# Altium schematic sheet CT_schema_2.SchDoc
size 307 x 173 mm
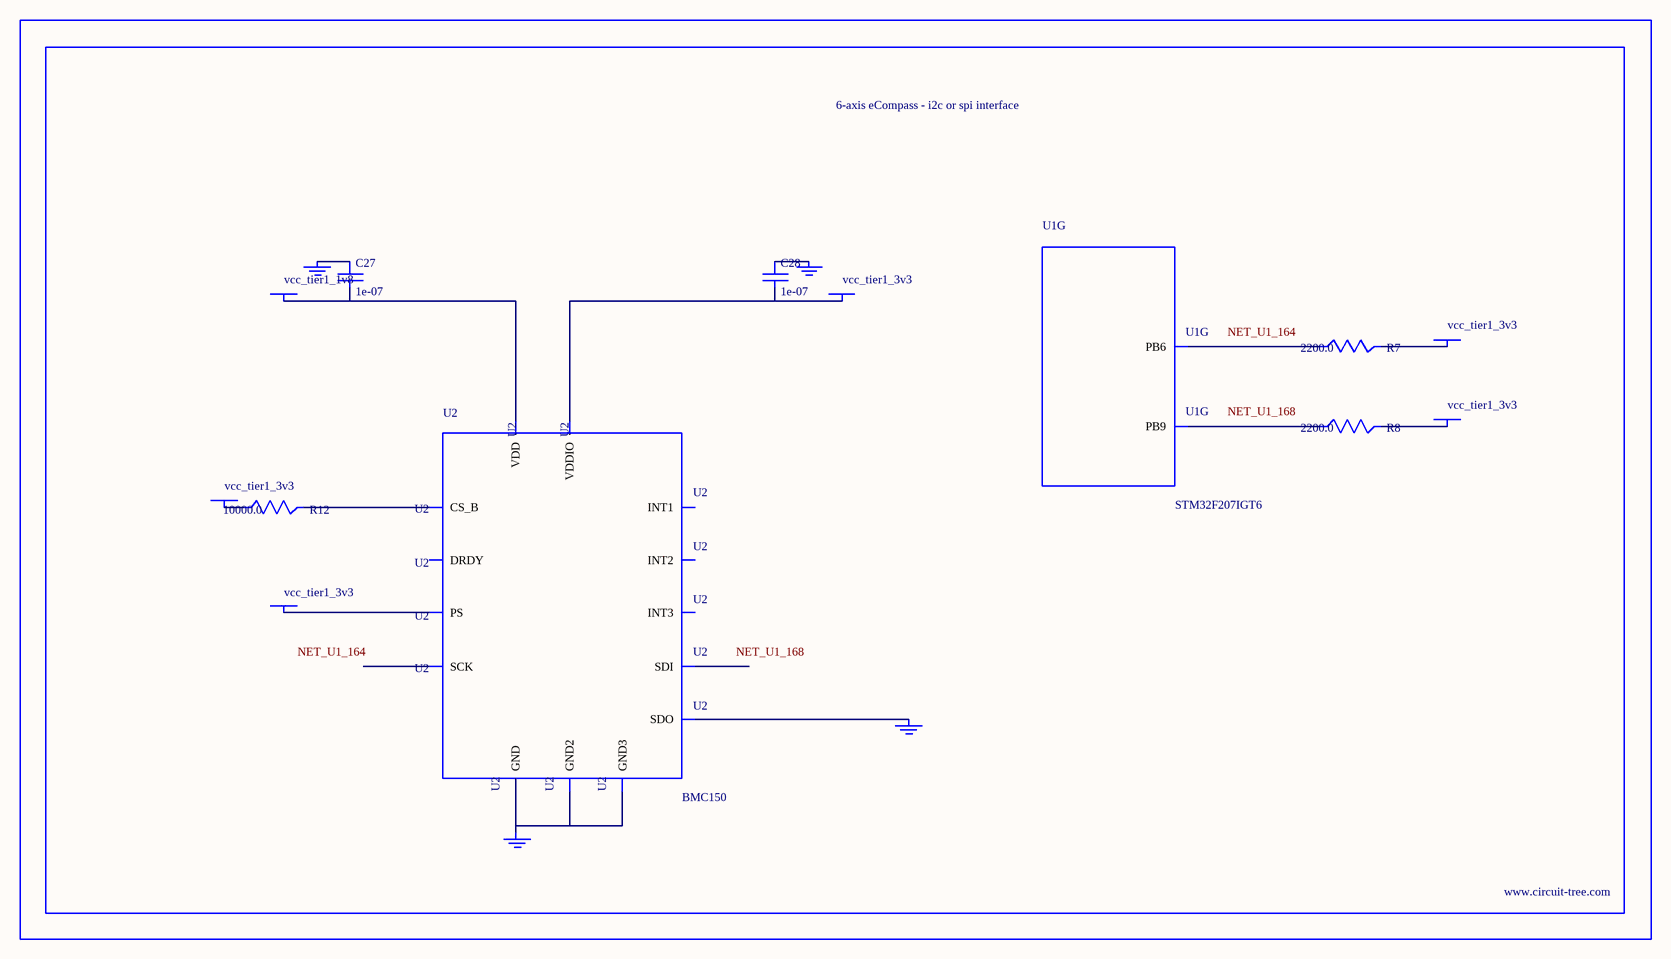
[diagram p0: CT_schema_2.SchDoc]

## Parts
BORDER1  (no value)
C27  1e-07  [C0402]
C28  1e-07  [C0402]
GND_INSTANCE_1_0  (no value)
GND_INSTANCE_1_1  (no value)
GND_INSTANCE_1_2  (no value)
GND_INSTANCE_1_3  (no value)
POWER_INSTANCE_1_0  vcc_tier1_1v8
POWER_INSTANCE_1_1  vcc_tier1_3v3
POWER_INSTANCE_1_2  vcc_tier1_3v3
POWER_INSTANCE_1_3  vcc_tier1_3v3
POWER_INSTANCE_1_4  vcc_tier1_3v3
POWER_INSTANCE_1_5  vcc_tier1_3v3
R7  2200.0  [R0603]
R8  2200.0  [R0603]
R12  10000.0  [R0603]
U1  STM32F207IGT6  [LQFP176]  (part G of 15)
U2  BMC150  [LGA14R35P5X6_200X200X100]

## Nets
NetC27_1: C27.1 GND_INSTANCE_1_1.0(GND)
NetC27_2: C27.2 POWER_INSTANCE_1_0.0(PWR) U2.8(VDD)
NetC28_1: C28.1 GND_INSTANCE_1_2.0(GND)
NetC28_2: C28.2 POWER_INSTANCE_1_1.0(PWR) U2.10(VDDIO)
NetGND_INSTANCE_1_0_0: GND_INSTANCE_1_0.0(GND) U2.1(SDO)
NetGND_INSTANCE_1_3_0: GND_INSTANCE_1_3.0(GND) U2.6(GND) U2.7(GND2) U2.9(GND3)
NetPOWER_INSTANCE_1_2_0: POWER_INSTANCE_1_2.0(PWR) R12.1
NetPOWER_INSTANCE_1_3_0: POWER_INSTANCE_1_3.0(PWR) U2.13(PS)
NetPOWER_INSTANCE_1_4_0: POWER_INSTANCE_1_4.0(PWR) R7.2
NetPOWER_INSTANCE_1_5_0: POWER_INSTANCE_1_5.0(PWR) R8.2
NetR7_1: R7.1 U1.164(PB6)
NetR8_1: R8.1 U1.168(PB9)
NetR12_2: R12.2 U2.12(CS_B)

Not connected (* = marked no-connect by the designer): U2 2(INT1) 3(INT2) 4(DRDY) 5(INT3) 11(SCK) 14(SDI)

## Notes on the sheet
- Labels drawn without touching a wire or pin: NET_U1_164, NET_U1_168

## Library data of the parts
BORDER1 = BORDER_PAGE1
C27 C28 = C0402C104K3RACTU
GND_INSTANCE_1_0-GND_INSTANCE_1_3 = GND
POWER_INSTANCE_1_0-POWER_INSTANCE_1_5 = PWR
R7 R8 = RC0603JR-072K2L
R12 = RC0603JR-0710KL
